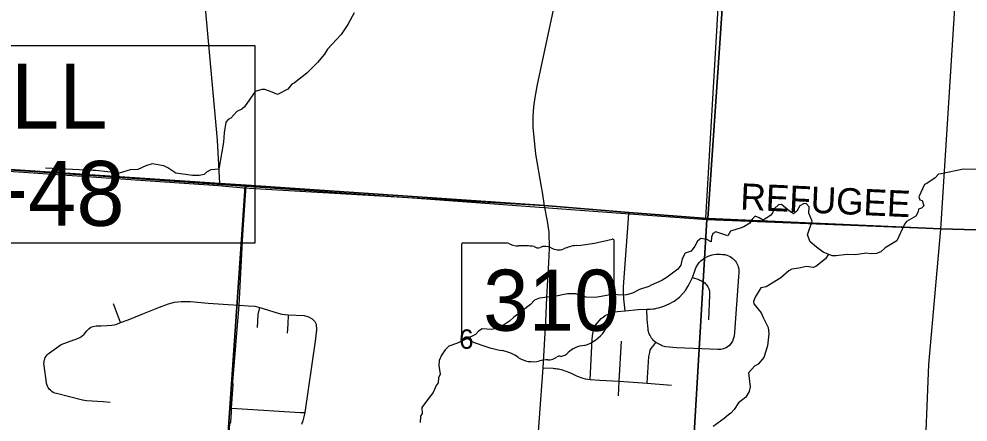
# Model space of a CAD drawing. Extents: x 0 to 34, y 0 to 22.
# Drawn here: x 4.778 to 6.826, y 17.784 to 18.654 of the extents above; entities that cross this region are included whole.
import ezdxf

# ---------------------------------------------------------------- set-up
doc = ezdxf.new("R2010")
doc.units = 0
for name, color, linetype in [('GM_X_City_Street', 7, 'Continuous'), ('GM_X_Corporation', 7, 'Continuous'), ('GM_X_Minor_River', 7, 'Continuous'), ('GM_X_Section', 7, 'Continuous'), ('GM_X_Section_Text', 7, 'Continuous'), ('GM_X_State_Location', 7, 'Continuous'), ('GM_X_State_Route', 7, 'Continuous'), ('GM_X_State_Shield', 7, 'Continuous'), ('GM_X_Township_Road', 7, 'Continuous'), ('GM_X_Township_Road_Text', 7, 'Continuous'), ('SH_Text', 7, 'Continuous')]:
    doc.layers.add(name, color=color, linetype=linetype)

msp = doc.modelspace()

# ---------------------------------------------------------------- linework, layer by layer
at = {"layer": 'GM_X_City_Street'}
msp.add_lwpolyline([(3.4177, 18.4149), (4.6284, 18.3336), (5.2084, 18.2946), (5.2627, 18.2891), (5.912, 18.251), (6.0938, 18.2359), (6.2605, 18.224), (6.3251, 19.3282)], dxfattribs=at)
at = {"layer": 'GM_X_Corporation'}
for points in [[(3.4218, 18.4152), (4.6285, 18.3373), (5.2113, 18.299), (5.2682, 18.2953), (5.912, 18.251), (6.0938, 18.2359), (6.2646, 18.2231), (6.3253, 19.1073), (6.3374, 19.2897), (6.3556, 19.5188), (6.3621, 19.6044), (6.385, 20.0884), (6.3883, 20.1254), (6.389, 20.1539), (6.3927, 20.2003), (6.4001, 20.2844), (6.4016, 20.3608), (6.4097, 20.4361), (6.4277, 20.7531), (6.4325, 20.8009), (6.4385, 20.9), (2.1, 20.9)], [(7.0679, 18.1923), (6.7672, 18.2007), (6.2646, 18.2231), (6.0938, 18.2359), (5.912, 18.251), (5.2682, 18.2953), (5.2113, 18.299), (4.6285, 18.3373), (3.4218, 18.4152)]]:
    msp.add_lwpolyline(points, dxfattribs=at)
msp.add_lwpolyline([(8.9, 18.0808), (8.9, 20.9), (6.4385, 20.9), (6.4325, 20.8009), (6.4277, 20.7531), (6.4097, 20.4361), (6.4016, 20.3608), (6.4001, 20.2844), (6.3927, 20.2003), (6.389, 20.1539), (6.3883, 20.1254), (6.385, 20.0884), (6.3621, 19.6044), (6.3556, 19.5188), (6.3374, 19.2897), (6.3253, 19.1073), (6.2646, 18.2231), (6.7672, 18.2007), (7.0679, 18.1923), (7.755, 18.1483), (7.8208, 18.1434), (8.8282, 18.0842)], close=True, dxfattribs=at)
at = {"layer": 'GM_X_Minor_River'}
for points in [[(5.5009, 18.6667), (5.4879, 18.6421), (5.4735, 18.6201), (5.4435, 18.5886)], [(5.4435, 18.5886), (5.4375, 18.578), (5.4223, 18.5598), (5.3991, 18.5367), (5.3722, 18.5159), (5.3669, 18.5133), (5.3578, 18.5023), (5.3358, 18.4906), (5.3244, 18.4959), (5.3086, 18.5016), (5.3021, 18.5017), (5.2873, 18.4975), (5.2642, 18.4642), (5.2589, 18.4592), (5.2482, 18.4543), (5.2353, 18.4396), (5.2293, 18.4365), (5.2243, 18.4312), (5.2205, 18.4077), (5.2193, 18.3876), (5.2094, 18.3299), (5.1919, 18.3281), (5.1828, 18.3228), (5.1772, 18.3179), (5.1669, 18.3156), (5.1525, 18.3156), (5.1162, 18.3207), (5.0992, 18.3328), (5.0901, 18.337), (5.0651, 18.3409), (5.0519, 18.3371), (5.0344, 18.3288), (5.0178, 18.3285), (4.9943, 18.3213), (4.9435, 18.3264), (4.9371, 18.3268), (4.8352, 18.3315)], [(6.8532, 18.3289), (6.8161, 18.3297), (6.768, 18.3196), (6.7627, 18.3188), (6.7551, 18.3109), (6.7373, 18.2984), (6.732, 18.2965), (6.7198, 18.27), (6.7224, 18.2635), (6.7273, 18.262), (6.7311, 18.2506), (6.7258, 18.2453), (6.7194, 18.2434), (6.7186, 18.2373), (6.7133, 18.2282), (6.6932, 18.2169), (6.689, 18.2108), (6.6723, 18.1752), (6.6472, 18.1597), (6.6377, 18.1513), (6.6283, 18.1476), (6.6146, 18.1468), (6.6071, 18.1484), (6.5824, 18.1446), (6.5654, 18.1454), (6.5415, 18.1428), (6.5332, 18.1425), (6.5135, 18.1501), (6.4992, 18.1611), (6.4852, 18.1726), (6.4795, 18.1881)], [(6.4795, 18.1881), (6.4894, 18.2177), (6.4827, 18.2344), (6.4831, 18.2481), (6.477, 18.2557), (6.471, 18.2546), (6.4634, 18.2504), (6.4569, 18.2387), (6.4493, 18.233), (6.4403, 18.2395), (6.4236, 18.2535), (6.4168, 18.2528), (6.4085, 18.2448), (6.4043, 18.235), (6.3997, 18.2293), (6.3842, 18.2195), (6.3751, 18.2248), (6.3664, 18.2279), (6.3603, 18.2218), (6.3554, 18.2127), (6.3425, 18.2051), (6.3368, 18.2033), (6.3133, 18.1957), (6.308, 18.1859), (6.2815, 18.1943), (6.2754, 18.1905), (6.2724, 18.1829), (6.2716, 18.173), (6.2625, 18.1776), (6.2497, 18.1803), (6.2421, 18.1742), (6.2364, 18.1636), (6.2288, 18.1523), (6.2155, 18.1485), (6.2094, 18.1364), (6.206, 18.1223), (6.1995, 18.114), (6.1768, 18.0962), (6.1654, 18.0894), (6.1423, 18.0792), (6.137, 18.0765), (6.1169, 18.0698), (6.1021, 18.0618), (6.0892, 18.0581), (6.0817, 18.0573), (6.057, 18.0593), (6.0343, 18.0551), (6.0214, 18.0525), (6.0021, 18.0533), (5.9794, 18.0602), (5.962, 18.0602), (5.9302, 18.0542), (5.9245, 18.0539), (5.9014, 18.0509), (5.8904, 18.0467), (5.8821, 18.0376), (5.8457, 18.0104), (5.8362, 18.0013), (5.8191, 17.99), (5.8134, 17.9869), (5.7986, 17.9836), (5.7778, 17.9851), (5.7695, 17.9798), (5.763, 17.973), (5.724, 17.9537), (5.7058, 17.9473), (5.6974, 17.9394), (5.6898, 17.928), (5.6845, 17.9166), (5.6841, 17.906), (5.6871, 17.8874), (5.6829, 17.8791), (5.6825, 17.8684), (5.678, 17.8624), (5.6715, 17.8476), (5.6613, 17.8347), (5.6472, 17.8154), (5.6479, 17.8025), (5.6445, 17.7964), (5.6437, 17.7827)], [(6.5247, 18.1458), (6.5188, 18.136), (6.4976, 18.1194), (6.4919, 18.1175), (6.4775, 18.1198), (6.4608, 18.1157), (6.4457, 18.1138), (6.4392, 18.1104), (6.4222, 18.0953), (6.3907, 18.0756), (6.379, 18.0737), (6.3664, 18.0536), (6.3634, 18.0442), (6.3637, 18.0392), (6.3796, 18.0198), (6.3841, 18.0096), (6.3871, 18.0039), (6.3951, 17.9879), (6.3962, 17.9739), (6.3931, 17.9481), (6.3855, 17.923), (6.3733, 17.909), (6.3654, 17.9041), (6.3597, 17.898), (6.3521, 17.8901), (6.3558, 17.8601), (6.3535, 17.8495), (6.3467, 17.8377), (6.3304, 17.8252), (6.3212, 17.8112), (6.314, 17.8029), (6.3091, 17.7994), (6.2996, 17.7911), (6.2761, 17.7741)]]:
    msp.add_lwpolyline(points, dxfattribs=at)
at = {"layer": 'GM_X_Section'}
for points in [[(4.2612, 18.3613), (4.4567, 18.3488), (4.4602, 18.3486), (4.9805, 18.3133), (5.2662, 18.2926), (5.2271, 17.7305), (4.7425, 17.7636), (4.2214, 17.7996)], [(5.2662, 18.2926), (5.3729, 18.2854), (5.6268, 18.2675), (6.2624, 18.2212), (6.2291, 17.6617), (5.7501, 17.6941), (5.2271, 17.7305)], [(6.2624, 18.2212), (6.7545, 18.2014), (7.2638, 18.1848), (7.2905, 18.1831), (7.2571, 17.593), (6.7148, 17.6287), (6.2291, 17.6617)]]:
    msp.add_lwpolyline(points, close=True, dxfattribs=at)
at = {"layer": 'GM_X_State_Route'}
for points in [[(5.9075, 18.2796), (5.9056, 18.2913), (5.8935, 18.3617), (5.8902, 18.3916), (5.8878, 18.4198), (5.8879, 18.4432), (5.8889, 18.464), (5.8919, 18.484), (5.8968, 18.512), (5.9396, 18.7109)], [(5.8853, 17.5875), (5.8935, 17.6853), (5.9091, 17.901), (5.9149, 18.0007), (5.9172, 18.0536), (5.9215, 18.1276), (5.9231, 18.1588), (5.9218, 18.1937), (5.9185, 18.2173), (5.9122, 18.2504), (5.9075, 18.2796)]]:
    msp.add_lwpolyline(points, dxfattribs=at)
at = {"layer": 'GM_X_State_Shield'}
for p, q in [((5.8325, 18.1702), (5.7359, 18.1702)), ((6.0623, 18.0705), (6.0623, 18.1752)), ((5.7327, 18.1668), (5.7327, 17.9667)), ((6.0623, 18.0705), (6.0623, 18.0705))]:
    msp.add_line(p, q, dxfattribs=at)
for centre, major_axis, start_param, end_param in [((5.7365, 18.1672), (0.00382, 0), 1.712693, 3.28349), ((5.8555, 18.1935), (0.037, 0), 4.042523, 4.731795), ((5.9449, 18.4431), (0.3495, 0), 4.814394, 5.042369), ((6.0586, 18.1756), (0.00367, 0), 6.141152, 7.989035), ((5.8677, 18.0579), (0.133, 0), 1.404758, 1.657858), ((5.8979, 18.1683), (0.0107, 0), 3.836095, 5.185415), ((5.9136, 18.1451), (0.0222, 0), 0.950623, 2.079405), ((5.9423, 18.1768), (0.0267, 0), 4.081561, 5.145723), ((5.9895, 18.1091), (0.0703, 0), 1.699011, 2.107814), ((6.0614, 18.0628), (0.00568, 0), 1.883978, 3.671073), ((6.0584, 18.0701), (0.00393, 0), 5.05454, 6.418171), ((6.0253, 18.0496), (0.0341, 0), 5.934695, 6.695948), ((6.0754, 18.0267), (0.0248, 0), 2.387724, 3.262537), ((5.9645, 18.0134), (0.0874, 0), 5.101752, 6.440018), ((5.7365, 17.9662), (0.00385, 0), 3.00124, 4.508301), ((5.7371, 17.9867), (0.0294, 0), 4.665946, 4.897461), ((5.7431, 17.9551), (0.0106, 0), 0.519207, 1.627899), ((5.8769, 18.1349), (0.2524, 0), 4.195997, 4.488961), ((6.0013, 17.9105), (0.0479, 0), 1.647645, 2.488434), ((5.8017, 17.8768), (0.079, 0), 0.823519, 1.323587), ((5.9197, 17.9391), (0.0267, 0), 4.691044, 5.507374), ((5.9439, 17.9198), (0.00752, 0), 1.147584, 2.315152), ((5.9407, 17.9473), (0.0282, 0), 4.937069, 5.64225), ((5.8871, 17.9541), (0.0501, 0), 4.026481, 4.996735), ((5.9161, 17.8849), (0.0412, 0), 1.495662, 1.94098)]:
    msp.add_ellipse(centre, major_axis=major_axis, ratio=0.8, start_param=start_param, end_param=end_param, dxfattribs=at)
at = {"layer": 'GM_X_Township_Road'}
for p, q in [((6.7674, 18.2001), (6.8177, 18.998)), ((5.2684, 18.2947), (5.2116, 18.2984)), ((5.9122, 18.2504), (5.2684, 18.2947)), ((4.9971, 17.9989), (4.9816, 18.0387)), ((6.0732, 17.872), (6.0784, 17.9584)), ((6.0719, 17.8401), (6.0732, 17.872))]:
    msp.add_line(p, q, dxfattribs=at)
for points in [[(5.2116, 18.2984), (5.2059, 18.3925), (5.1805, 18.6769), (5.1777, 18.6909), (5.1724, 18.7062), (5.1629, 18.7337), (5.0721, 18.9955), (5.0684, 19.0065), (5.0666, 19.0147), (5.067, 19.0245), (5.0644, 19.1757), (5.0714, 19.2876), (5.0958, 19.6447)], [(5.2116, 18.2984), (4.6288, 18.3368), (3.4221, 18.4146)], [(5.1991, 17.243), (5.1996, 17.2528), (5.2054, 17.3455), (5.21, 17.413), (5.2152, 17.4824), (5.2171, 17.5084), (5.2172, 17.5123), (5.2246, 17.6696), (5.2326, 17.78), (5.2351, 17.7833), (5.2368, 17.8055), (5.2368, 17.8139), (5.2401, 17.865), (5.2392, 17.8706), (5.2531, 18.0362), (5.2612, 18.1878), (5.2684, 18.2947)], [(6.2638, 18.2226), (6.094, 18.2354), (5.9122, 18.2504)], [(6.0861, 18.0241), (6.0832, 18.0496), (6.0822, 18.0641), (6.0825, 18.0757), (6.0935, 18.223), (6.094, 18.2354)], [(6.7674, 18.2001), (6.2648, 18.2225), (6.2638, 18.2226)], [(6.7254, 17.2668), (6.7258, 17.2749), (6.7316, 17.3909), (6.7455, 17.5846), (6.7423, 17.6154), (6.7415, 17.6181), (6.7401, 17.6235), (6.7327, 17.6404), (6.7315, 17.654), (6.7322, 17.6746), (6.7412, 17.9082), (6.7674, 18.2001)], [(7.821, 18.1428), (7.7552, 18.1477), (7.0681, 18.1918), (6.7674, 18.2001)], [(6.0104, 17.8758), (6.0152, 17.961), (6.0155, 17.9706), (6.016, 17.9745), (6.0175, 17.9812), (6.02, 17.9876), (6.0224, 17.9926), (6.0262, 17.9982), (6.0297, 18.0024), (6.0345, 18.0073), (6.0385, 18.0104), (6.0431, 18.0134), (6.0491, 18.0165), (6.0539, 18.0182), (6.06, 18.0206), (6.0697, 18.0224), (6.0861, 18.0241), (6.1142, 18.0264), (6.1331, 18.0272), (6.1401, 18.0274), (6.1461, 18.0281), (6.1494, 18.0285), (6.1539, 18.0295), (6.158, 18.0304), (6.1693, 18.0338), (6.1813, 18.0387), (6.1922, 18.0447), (6.2034, 18.0536), (6.2106, 18.0611), (6.2161, 18.0677), (6.2215, 18.0766), (6.225, 18.0826), (6.2313, 18.0958), (6.2364, 18.1105), (6.2379, 18.1146), (6.2397, 18.1183), (6.2429, 18.1237), (6.246, 18.1278), (6.2494, 18.1314), (6.2521, 18.1339), (6.2551, 18.1363), (6.2586, 18.1387), (6.2623, 18.1406), (6.2656, 18.1421), (6.2696, 18.1435), (6.2739, 18.1448), (6.2778, 18.1456), (6.2828, 18.146), (6.2888, 18.146), (6.2921, 18.1459), (6.2963, 18.1456), (6.3012, 18.1452), (6.3053, 18.144), (6.3091, 18.1426), (6.3124, 18.1409), (6.3154, 18.1391), (6.3188, 18.1365), (6.3213, 18.1338), (6.3234, 18.1315), (6.3254, 18.1289), (6.3273, 18.1258), (6.329, 18.1219), (6.3302, 18.1185), (6.3312, 18.1145), (6.3316, 18.11), (6.3316, 18.1058), (6.3311, 18.0975), (6.3219, 17.9776), (6.3213, 17.9693), (6.3179, 17.9584), (6.311, 17.9492), (6.3043, 17.9443), (6.3021, 17.9432), (6.2999, 17.9424), (6.2984, 17.9418), (6.2956, 17.9411), (6.2927, 17.9407), (6.2892, 17.9403), (6.2858, 17.9403), (6.2518, 17.9417), (6.1968, 17.9442), (6.1739, 17.9459), (6.1705, 17.9467), (6.1675, 17.9477), (6.1646, 17.9491), (6.1621, 17.9504), (6.1595, 17.952), (6.1521, 17.9555), (6.149, 17.958), (6.1468, 17.9604), (6.1449, 17.9624), (6.1433, 17.9646), (6.1413, 17.9677), (6.1399, 17.9703), (6.1388, 17.9724), (6.1374, 17.9763), (6.1366, 17.9789), (6.136, 17.9813), (6.1355, 17.9852), (6.1333, 18.0048), (6.1331, 18.0272)], [(6.2313, 18.0958), (6.2454, 18.0911), (6.2476, 18.0903), (6.2508, 18.0889), (6.2534, 18.0874), (6.2558, 18.0858), (6.258, 18.084), (6.2597, 18.0823), (6.2618, 18.0797), (6.2646, 18.0755), (6.2666, 18.071), (6.2678, 18.0667), (6.2684, 18.0621), (6.2685, 18.0579), (6.2657, 18.0046)], [(4.8687, 17.9512), (4.8823, 17.9565), (4.8958, 17.9611), (4.8991, 17.9623), (4.909, 17.9661), (4.9136, 17.9688), (4.9182, 17.9735), (4.9239, 17.9804), (4.9284, 17.985), (4.933, 17.9883), (4.9376, 17.9901), (4.9444, 17.9915), (4.9546, 17.9917), (4.9681, 17.9924), (4.978, 17.9929), (4.9838, 17.9934), (4.9889, 17.9947), (4.9971, 17.9989), (5.0132, 18.0046), (5.0451, 18.0175), (5.0814, 18.0318), (5.1007, 18.0387), (5.1136, 18.0422), (5.1281, 18.0441), (5.1477, 18.0441), (5.1862, 18.0406), (5.2291, 18.0374), (5.2531, 18.0362)], [(5.2531, 18.0362), (5.2727, 18.0349), (5.2869, 18.0336), (5.2973, 18.0308), (5.3144, 18.0257), (5.3321, 18.0204), (5.345, 18.0166), (5.3595, 18.015), (5.3933, 18.0141), (5.4028, 18.0112), (5.4107, 18.0065), (5.4164, 18.0005), (5.4192, 17.9948), (5.4202, 17.9828), (5.417, 17.9585), (5.3944, 17.8041), (5.3926, 17.7953), (5.3903, 17.7864), (5.3873, 17.7782)], [(5.2926, 17.9879), (5.2942, 18.016), (5.2973, 18.0308)], [(5.3576, 17.9759), (5.3587, 17.9947), (5.3595, 18.015)], [(4.9743, 17.8263), (4.9593, 17.8274), (4.9238, 17.8298), (4.9193, 17.8303), (4.9148, 17.8312), (4.8586, 17.8451), (4.855, 17.8462), (4.8516, 17.8478), (4.8485, 17.8498), (4.8456, 17.8523), (4.8431, 17.855), (4.841, 17.8581), (4.8393, 17.8614), (4.838, 17.865), (4.8373, 17.8686), (4.8319, 17.9061), (4.8316, 17.9096), (4.8318, 17.913), (4.8323, 17.9164), (4.8333, 17.9197), (4.8346, 17.9229), (4.8364, 17.9259), (4.8385, 17.9286), (4.8409, 17.9311), (4.8435, 17.9333), (4.8687, 17.9512)], [(6.1334, 17.8674), (6.1375, 17.9254), (6.1392, 17.934), (6.14, 17.9386), (6.1423, 17.9426), (6.1461, 17.9472), (6.1521, 17.9555)], [(5.9091, 17.901), (5.931, 17.8999), (5.9335, 17.8997), (5.9368, 17.8993), (5.9396, 17.899), (5.9423, 17.8985), (5.948, 17.8972), (5.951, 17.8963), (5.9539, 17.8954), (5.9585, 17.8937), (5.9622, 17.8921), (5.9713, 17.8883), (5.9797, 17.8844), (5.9825, 17.883), (5.9945, 17.8784), (5.9999, 17.8768), (6.0053, 17.8761), (6.0104, 17.8758), (6.0313, 17.8745)], [(6.0313, 17.8745), (6.0732, 17.872), (6.1334, 17.8674), (6.1859, 17.8634)], [(5.2368, 17.8139), (5.2479, 17.8129), (5.3856, 17.8042), (5.3944, 17.8041)]]:
    msp.add_lwpolyline(points, dxfattribs=at)
at = {"layer": 'SH_Text'}
msp.add_lwpolyline([(3.9683, 18.5968), (5.2868, 18.5968), (5.2868, 18.1701), (3.9683, 18.1701)], close=True, dxfattribs=at)

# ---------------------------------------------------------------- texts
at = {"layer": 'GM_X_Section_Text'}
msp.add_text('6', height=0.0419, rotation=0, dxfattribs=at).set_placement((5.7278, 17.9419))
at = {"layer": 'GM_X_State_Location'}
for s in ['s', 'r']:
    msp.add_text(s, height=0.000189, dxfattribs=at).set_placement((5.8938, 18.0534))
msp.add_text('310', height=0.000189, rotation=0, dxfattribs=at).set_placement((5.8269, 18.0396))
at = {"layer": 'GM_X_State_Shield'}
msp.add_text('310', height=0.13184, dxfattribs=at).set_placement((5.7797, 17.9808))
at = {"layer": 'GM_X_Township_Road_Text'}
msp.add_text('REFUGEE', height=0.05682, rotation=357.4046, dxfattribs=at).set_placement((6.3338, 18.2425))
at = {"layer": 'SH_Text'}
for s, p in [('END WALL      ', (4.0118, 18.4173)), ('STA. 13+48     ', (4.0118, 18.2073))]:
    msp.add_text(s, height=0.14, dxfattribs=at).set_placement(p)

doc.saveas('drawing.dxf')
